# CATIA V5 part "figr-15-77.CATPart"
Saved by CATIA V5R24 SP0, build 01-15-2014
Part number: Part1
Bounding box of the stored display mesh (mm): x -59.264 to 75.079, y -54.323 to 58.486, z 0 to 41.762
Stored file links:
  D:\KAVITA\CATIA V5-6R2014 Project_ Kavita\CATIA V5-6R2014_partfiles\Partfiles\c15_catia_v5-6r2014_prt\figr-15-77.CATPart
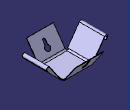
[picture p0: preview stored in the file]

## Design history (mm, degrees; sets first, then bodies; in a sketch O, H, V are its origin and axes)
SheetMetalParameters1: Thickness 1, BendRadius 5, KFactor 0.5 {= log(min(100,max(20*SheetMetalParameters1.BendRadius,SheetMetalParameters1.Thickness)/SheetMetalParameters1.Thickness))/log(100)/2}, ReliefRadialLength 1, ReliefAxialLength 2, MinimumBendRadius 0
Body1 (main body)
  Sketch1 on xy-plane, origin (0, 0, 0), H (1, 0, 0), V (0, 1, 0)
    line L1 (-24.5181, 30.1968) -> (40.3332, 30.1968)
    line L2 (40.3332, 30.1968) -> (40.3332, -26.0343)
    line L3 (40.3332, -26.0343) -> (-24.5181, -26.0343)
    line L4 (-24.5181, -26.0343) -> (-24.5181, 30.1968)
    horizontal: L1 H, L3 H
    vertical: L2 V, L4 V
  Wall1: Thickness 1, Profile Sketch1
  d_NewWallOnEdge1: NewWallOnEdge_Edge edge [face of Wall1 | face of Wall1], NewWallOnEdge_Length 40.2311, NewWallOnEdge_HeightLimitOffset 0, NewWallOnEdge_WidthOffset1 0, NewWallOnEdge_WidthOffset2 0, NewWallOnEdge_Angle 125, NewWallOnEdge_BendRadiusValue 5 {= SheetMetalParameters1.BendRadius}, NewWallOnEdge_BendTable SheetMetalParameters1, KFacteur 0.5 {= log(min(100,max(20*d_NewWallOnEdge1.Radius,SheetMetalParameters1.Thickness)/SheetMetalParameters1.Thickness))/log(100)/2}
  d_NewWallOnEdge2: NewWallOnEdge_Edge edge [face of Wall1 | face of Wall1], NewWallOnEdge_Length 40.2311, NewWallOnEdge_HeightLimitOffset 0, NewWallOnEdge_WidthOffset1 0, NewWallOnEdge_WidthOffset2 0, NewWallOnEdge_Angle 125, NewWallOnEdge_BendRadiusValue 5 {= SheetMetalParameters1.BendRadius}, NewWallOnEdge_BendTable SheetMetalParameters1, KFacteur 0.5 {= log(min(100,max(20*d_NewWallOnEdge2.Radius,SheetMetalParameters1.Thickness)/SheetMetalParameters1.Thickness))/log(100)/2}
  d_NewWallOnEdge3: NewWallOnEdge_Edge edge [face of Wall1 | face of Wall1], NewWallOnEdge_Length 40.2311, NewWallOnEdge_HeightLimitOffset 0, NewWallOnEdge_WidthOffset1 0, NewWallOnEdge_WidthOffset2 0, NewWallOnEdge_Angle 125, NewWallOnEdge_BendRadiusValue 5 {= SheetMetalParameters1.BendRadius}, NewWallOnEdge_BendTable SheetMetalParameters1, KFacteur 0.5 {= log(min(100,max(20*d_NewWallOnEdge3.Radius,SheetMetalParameters1.Thickness)/SheetMetalParameters1.Thickness))/log(100)/2}
  d_NewWallOnEdge4: NewWallOnEdge_Edge edge [face of Wall1 | face of Wall1], NewWallOnEdge_Length 40.2311, NewWallOnEdge_HeightLimitOffset 0, NewWallOnEdge_WidthOffset1 0, NewWallOnEdge_WidthOffset2 0, NewWallOnEdge_Angle 125, NewWallOnEdge_BendRadiusValue 5 {= SheetMetalParameters1.BendRadius}, NewWallOnEdge_BendTable SheetMetalParameters1, KFacteur 0.5 {= log(min(100,max(20*d_NewWallOnEdge4.Radius,SheetMetalParameters1.Thickness)/SheetMetalParameters1.Thickness))/log(100)/2}
  Sketch2 on face of d_NewWallOnEdge4, origin (0, -16.9994, -11.9031), H (-1, 0, 0), V (0, -0.5736, 0.8192)
    construction line L1 (-8.3417, 33.0355) -> (-8.3417, 47.6528)
    line L2 (-5.6402, 47.6528) -> (-5.6402, 38.4491)
    line L3 (-11.0431, 38.4491) -> (-11.0431, 47.6528)
    arc A1 centre (-8.3417, 33.0355) radius 6.0503 from (-5.6402, 38.4491) to (-11.0431, 38.4491) cw
    arc A2 centre (-8.3417, 47.6528) radius 2.7015 from (-11.0431, 47.6528) to (-5.6402, 47.6528) cw
    radius A1 = 6.0503
    radius A2 = 2.7015
    vertical: L1 V
    tangency: A2 L2, A2 L3
    parallelism: L2 L3, L2 L1
  CutOut1: Direction Sketch2, EndLimit through (limit type 3), Orientation false, Profile Sketch2, StartLimit through (limit type 2)
  Sketch3 on face of d_NewWallOnEdge2, origin (0, 19.7925, -13.8589), H (1, 0, 0), V (0, 0.5736, 0.8192)
    construction line L1 (6.0153, 41.1403) -> (6.0153, 57.8706)
    line L2 (8.7383, 57.8706) -> (8.7383, 46.3808)
    line L3 (3.2923, 46.3808) -> (3.2923, 57.8706)
    arc A1 centre (6.0153, 41.1403) radius 5.9058 from (8.7383, 46.3808) to (3.2923, 46.3808) cw
    arc A2 centre (6.0153, 57.8706) radius 2.723 from (3.2923, 57.8706) to (8.7383, 57.8706) cw
    radius A1 = 5.9058
    radius A2 = 2.723
    vertical: L1 V
    tangency: A2 L2, A2 L3
    parallelism: L2 L3, L2 L1
  CutOut2: Direction Sketch3, EndLimit through (limit type 3), Orientation true, Profile Sketch3, StartLimit through (limit type 2)
  Flange1: Angle 90, Length 5, Radius 3, KFacteur 0.444538 {= log(min(100,max(20*Flange1.Radius,SheetMetalParameters1.Thickness)/SheetMetalParameters1.Thickness))/log(100)/2}, Guide edge [face of d_NewWallOnEdge1 | face of d_NewWallOnEdge1]
  Flange2: Angle 90, Length 5, Radius 3, KFacteur 0.444538 {= log(min(100,max(20*Flange2.Radius,SheetMetalParameters1.Thickness)/SheetMetalParameters1.Thickness))/log(100)/2}, Guide edge [face of d_NewWallOnEdge3 | face of d_NewWallOnEdge3]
